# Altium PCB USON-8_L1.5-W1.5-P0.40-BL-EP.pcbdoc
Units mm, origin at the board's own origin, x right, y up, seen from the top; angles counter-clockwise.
Board outline 14.63 x 14.79 mm, 2 copper layers (Top Layer, Bottom Layer), stack 0 mm thick; 1 components, 0 nets, 9 pads, 0 vias.
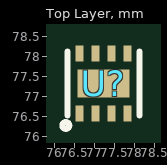
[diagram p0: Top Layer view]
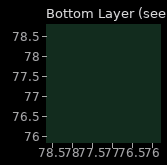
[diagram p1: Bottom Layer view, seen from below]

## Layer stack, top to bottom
Top Layer: signal copper (thickness not stored)
Bottom Layer: signal copper (thickness not stored)

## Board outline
84.475,69.85 69.85,69.85 69.85,84.635 84.475,84.635

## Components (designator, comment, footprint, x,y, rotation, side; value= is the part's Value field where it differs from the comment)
U? "" USON-8_L1.5-W1.5-P0.40-BL-EP 77.225,77.335 r0 top

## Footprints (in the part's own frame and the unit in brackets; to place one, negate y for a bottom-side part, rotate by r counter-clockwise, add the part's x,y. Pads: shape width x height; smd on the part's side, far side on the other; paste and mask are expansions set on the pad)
USON-8_L1.5-W1.5-P0.40-BL-EP [mm]
  rect 0.2x0.4 smd: 1(-0.6,-0.75) 2(-0.2,-0.75) 3(0.2,-0.75) 4(0.6,-0.75) 5(0.6,0.75) 6(0.2,0.75) 7(-0.2,0.75) 8(-0.6,0.75)
  rect 1.3x0.7 smd: 9(0,0)
  silkscreen extent -1.03,-1.14 0.9,0.8

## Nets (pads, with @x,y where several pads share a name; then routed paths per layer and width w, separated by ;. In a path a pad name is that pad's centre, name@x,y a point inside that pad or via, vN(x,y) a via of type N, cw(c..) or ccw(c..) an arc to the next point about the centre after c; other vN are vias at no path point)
pads on no net: U?.1 U?.2 U?.3 U?.4 U?.5 U?.6 U?.7 U?.8 U?.9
